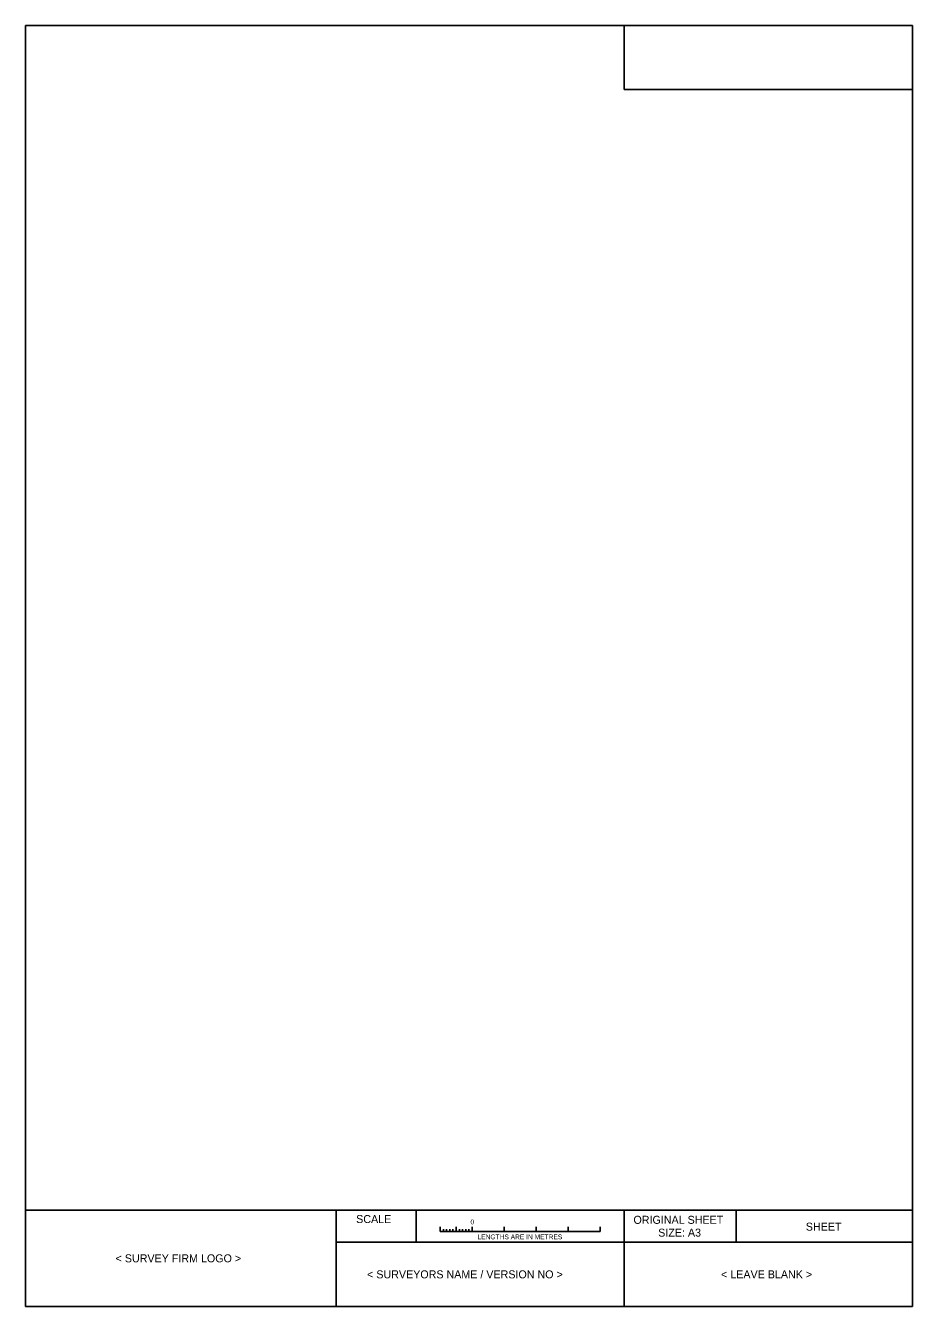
# Model space of a CAD drawing. Extents: x 0.01 to 0.287, y 0.01 to 0.41.
import ezdxf

# ---------------------------------------------------------------- set-up
doc = ezdxf.new("R2010")
doc.units = 0
for name, color, linetype in [('Proforma major line', 7, 'Continuous'), ('Proforma minor line', 7, 'Continuous'), ('Proforma text', 7, 'Continuous'), ('Scale', 7, 'Continuous')]:
    doc.layers.add(name, color=color, linetype=linetype)

msp = doc.modelspace()

# ---------------------------------------------------------------- linework, layer by layer
at = {"layer": 'Proforma major line'}
for p, q in [((0.287, 0.41), (0.01, 0.41)), ((0.01, 0.01), (0.01, 0.41)), ((0.287, 0.01), (0.287, 0.41)), ((0.01, 0.04), (0.287, 0.04)), ((0.01, 0.01), (0.287, 0.01))]:
    msp.add_line(p, q, dxfattribs=at)
at = {"layer": 'Proforma minor line'}
for p, q in [((0.197, 0.41), (0.197, 0.39)), ((0.197, 0.39), (0.287, 0.39)), ((0.107, 0.04), (0.107, 0.03)), ((0.132, 0.03), (0.132, 0.04)), ((0.197, 0.04), (0.197, 0.01)), ((0.232, 0.03), (0.232, 0.04)), ((0.107, 0.03), (0.107, 0.01)), ((0.107, 0.03), (0.197, 0.03)), ((0.197, 0.03), (0.287, 0.03))]:
    msp.add_line(p, q, dxfattribs=at)
at = {"layer": 'Scale'}
for p, q in [((0.1395, 0.03334), (0.1395, 0.03484)), ((0.1895, 0.03334), (0.1395, 0.03334)), ((0.1405, 0.03409), (0.1405, 0.03334)), ((0.1415, 0.03409), (0.1415, 0.03334)), ((0.1425, 0.03409), (0.1425, 0.03334)), ((0.1435, 0.03409), (0.1435, 0.03334)), ((0.1445, 0.03484), (0.1445, 0.03334)), ((0.1455, 0.03409), (0.1455, 0.03334)), ((0.1465, 0.03409), (0.1465, 0.03334)), ((0.1475, 0.03409), (0.1475, 0.03334)), ((0.1485, 0.03409), (0.1485, 0.03334)), ((0.1495, 0.03334), (0.1495, 0.03484)), ((0.1595, 0.03334), (0.1595, 0.03484)), ((0.1695, 0.03334), (0.1695, 0.03484)), ((0.1795, 0.03334), (0.1795, 0.03484)), ((0.1895, 0.03334), (0.1895, 0.03484))]:
    msp.add_line(p, q, dxfattribs=at)

# ---------------------------------------------------------------- texts
at = {"layer": 'Proforma text'}
for s, p in [('SCALE', (0.11326, 0.03602)), ('ORIGINAL SHEET', (0.19988, 0.03578)), ('SHEET', (0.25372, 0.03365)), ('SIZE: A3', (0.2076, 0.03178)), ('< SURVEY FIRM LOGO >', (0.03812, 0.02375)), ('< SURVEYORS NAME / VERSION NO >', (0.11667, 0.01875)), ('< LEAVE BLANK >', (0.22725, 0.01875))]:
    msp.add_text(s, height=0.0025, dxfattribs=at).set_placement(p)
at = {"layer": 'Scale'}
for s, p in [('0', (0.14897, 0.03561)), ('LENGTHS ARE IN METRES', (0.15117, 0.03095))]:
    msp.add_text(s, height=0.0015, dxfattribs=at).set_placement(p)

doc.saveas('drawing.dxf')
